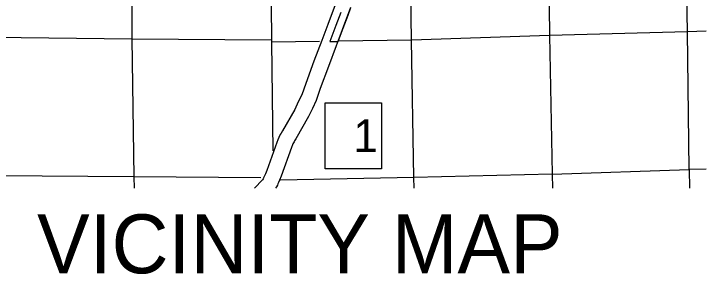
# Model space of a CAD drawing. Extents: x 1369885 to 1370219, y 379980 to 380218.
# Drawn here: x 1369916.19 to 1369958.99, y 380132.36 to 380148.46 of the extents above; entities that cross this region are included whole.
import ezdxf

# ---------------------------------------------------------------- set-up
doc = ezdxf.new("R2010")
doc.units = 0
for name, color, linetype in [('Default', 7, 'Continuous'), ('Level 10', 7, 'Continuous'), ('Level 27', 7, 'Continuous'), ('Level 4', 7, 'Continuous'), ('Level 5', 7, 'Continuous'), ('Level 6', 7, 'Continuous')]:
    doc.layers.add(name, color=color, linetype=linetype)

msp = doc.modelspace()

# ---------------------------------------------------------------- linework, layer by layer
at = {"layer": 'Level 10'}
for points in [[(1369936.108, 380149.178), (1369935.591, 380147.802), (1369935.219, 380146.817), (1369934.736, 380145.541), (1369934.23, 380144.162), (1369933.983, 380143.462), (1369933.773, 380143.02), (1369933.559, 380142.548), (1369932.806, 380141.232), (1369932.708, 380141.089), (1369932.662, 380140.993), (1369932.566, 380140.818), (1369932.513, 380140.678), (1369932.455, 380140.506), (1369931.834, 380138.782), (1369931.742, 380138.575), (1369931.665, 380138.406), (1369931.631, 380138.322), (1369931.618, 380138.291), (1369931.6, 380138.26), (1369931.593, 380138.248), (1369931.557, 380138.206), (1369931.063, 380137.69)], [(1369937.006, 380148.844), (1369936.488, 380147.464), (1369936.116, 380146.478), (1369935.634, 380145.206), (1369935.131, 380143.837), (1369934.87, 380143.095), (1369934.642, 380142.617), (1369934.413, 380142.111), (1369933.619, 380140.723), (1369933.541, 380140.61), (1369933.516, 380140.556), (1369933.439, 380140.416), (1369933.416, 380140.355), (1369933.359, 380140.189), (1369932.724, 380138.424), (1369932.616, 380138.182), (1369932.545, 380138.025), (1369932.515, 380137.952), (1369932.481, 380137.873), (1369932.426, 380137.773), (1369932.374, 380137.69)]]:
    msp.add_lwpolyline(points, dxfattribs=at)
at = {"layer": 'Level 27'}
msp.add_lwpolyline([(1369935.431, 380142.967), (1369938.92, 380142.967), (1369938.92, 380138.879), (1369935.431, 380138.879)], close=True, dxfattribs=at)
at = {"layer": 'Level 4'}
msp.add_lwpolyline([(1369932.023, 380156.54), (1369932.037, 380155.354), (1369932.115, 380146.851), (1369932.126, 380146.707), (1369932.199, 380139.989)], dxfattribs=at)
at = {"layer": 'Level 5'}
for points in [[(1369957.927, 380138.826), (1369957.838, 380147.346), (1369957.682, 380155.37)], [(1369940.922, 380138.331), (1369940.769, 380146.823), (1369940.695, 380152.485)], [(1369923.496, 380152.058), (1369923.487, 380146.925), (1369923.615, 380138.382)], [(1369949.234, 380152.414), (1369949.311, 380147.12), (1369949.472, 380138.551), (1369940.922, 380138.331), (1369932.672, 380138.177)], [(1369957.838, 380147.346), (1369949.311, 380147.12), (1369940.769, 380146.823), (1369936.266, 380146.763)], [(1369958.986, 380147.39), (1369957.838, 380147.346)], [(1369911.437, 380147.015), (1369914.904, 380147.01), (1369923.487, 380146.925), (1369932.115, 380146.851)], [(1369935.092, 380146.747), (1369932.126, 380146.707)], [(1369949.472, 380138.551), (1369957.927, 380138.826)], [(1369958.986, 380138.862), (1369957.927, 380138.826)], [(1369957.927, 380138.826), (1369957.954, 380137.69)], [(1369931.463, 380138.317), (1369923.615, 380138.382), (1369915.071, 380138.448), (1369906.458, 380138.378), (1369906.118, 380138.377)], [(1369923.615, 380138.382), (1369923.622, 380137.69)], [(1369940.937, 380137.69), (1369940.922, 380138.331)], [(1369949.472, 380138.551), (1369949.481, 380137.69)]]:
    msp.add_lwpolyline(points, dxfattribs=at)
at = {"layer": 'Level 6'}
msp.add_lwpolyline([(1369936.411, 380148.55), (1369936.093, 380147.74), (1369935.73, 380146.75), (1369936.243, 380146.758), (1369936.541, 380147.57), (1369936.859, 380148.38), (1369937.031, 380148.852)], dxfattribs=at)

# ---------------------------------------------------------------- texts
at = {"layer": 'Default'}
msp.add_text('VICINITY MAP', height=3.64368, dxfattribs=at).set_placement((1369917.626, 380132.416))
at = {"layer": 'Level 27'}
msp.add_text('1', height=2.024, dxfattribs=at).set_placement((1369937.176, 380139.911))

doc.saveas('drawing.dxf')
